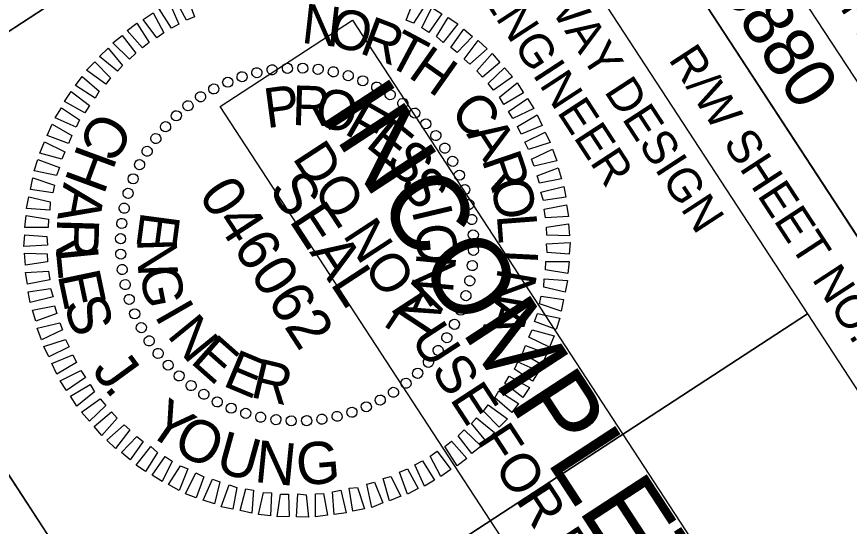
# Model space of a CAD drawing. Extents: x 1639622 to 2864602, y 842655 to 973236.
# Drawn here: x 1641227.1 to 1641350.8, y 843286.8 to 843362.5 of the extents above; entities that cross this region are included whole.
import ezdxf

# ---------------------------------------------------------------- set-up
doc = ezdxf.new("R2010")
doc.units = 0
for name, color, linetype in [('Default', 7, 'Continuous'), ('Old_Level_2', 7, 'Continuous'), ('Sheet Data Field CELL', 7, 'Continuous'), ('Sheet Plan CELL', 7, 'Continuous'), ('Sheet Sticker Exception Certification CELL', 7, 'Continuous'), ('Sheet Sticker Incomplete CELL', 7, 'Continuous')]:
    doc.layers.add(name, color=color, linetype=linetype)

msp = doc.modelspace()

# ---------------------------------------------------------------- linework, layer by layer
at = {"layer": 'Old_Level_2'}
for p, q in [((1641265.06, 843354.65), (1641265.06, 843354.65)), ((1641267.33, 843354.93), (1641267.33, 843354.93)), ((1641269.63, 843354.91), (1641269.63, 843354.91)), ((1641271.93, 843354.76), (1641271.93, 843354.76)), ((1641260.57, 843353.63), (1641260.57, 843353.63)), ((1641262.8, 843354.26), (1641262.8, 843354.26)), ((1641274.15, 843354.38), (1641274.15, 843354.38)), ((1641276.42, 843353.83), (1641276.42, 843353.83)), ((1641258.49, 843352.79), (1641258.49, 843352.79)), ((1641278.53, 843353.05), (1641278.53, 843353.05)), ((1641280.64, 843352.08), (1641280.64, 843352.08)), ((1641256.42, 843351.83), (1641256.42, 843351.83)), ((1641282.65, 843350.97), (1641282.65, 843350.97)), ((1641254.43, 843350.67), (1641254.43, 843350.67)), ((1641284.52, 843349.71), (1641284.52, 843349.71)), ((1641252.56, 843349.34), (1641252.56, 843349.34)), ((1641250.87, 843347.82), (1641250.87, 843347.82)), ((1641286.27, 843348.25), (1641286.27, 843348.25)), ((1641249.2, 843346.18), (1641249.2, 843346.18)), ((1641287.9, 843346.58), (1641287.9, 843346.58)), ((1641289.43, 843344.89), (1641289.43, 843344.89)), ((1641247.73, 843344.43), (1641247.73, 843344.43)), ((1641246.47, 843342.56), (1641246.47, 843342.56)), ((1641290.76, 843343.02), (1641290.76, 843343.02)), ((1641291.92, 843341.02), (1641291.92, 843341.02)), ((1641245.37, 843340.55), (1641245.37, 843340.55)), ((1641244.4, 843338.44), (1641244.4, 843338.44)), ((1641292.88, 843338.96), (1641292.88, 843338.96)), ((1641243.62, 843336.33), (1641243.62, 843336.33)), ((1641293.72, 843336.87), (1641293.72, 843336.87)), ((1641243.07, 843334.07), (1641243.07, 843334.07)), ((1641294.35, 843334.65), (1641294.35, 843334.65)), ((1641294.74, 843332.39), (1641294.74, 843332.39)), ((1641242.68, 843331.85), (1641242.68, 843331.85)), ((1641295.02, 843330.11), (1641295.02, 843330.11)), ((1641242.54, 843329.54), (1641242.54, 843329.54)), ((1641268.77, 843328.68), (1641268.77, 843328.68)), ((1641294.99, 843327.82), (1641294.99, 843327.82)), ((1641242.51, 843327.25), (1641242.51, 843327.25)), ((1641242.79, 843324.97), (1641242.79, 843324.97)), ((1641294.85, 843325.51), (1641294.85, 843325.51)), ((1641243.19, 843322.71), (1641243.19, 843322.71)), ((1641294.46, 843323.29), (1641294.46, 843323.29)), ((1641243.81, 843320.48), (1641243.81, 843320.48)), ((1641293.91, 843321.02), (1641293.91, 843321.02)), ((1641293.13, 843318.92), (1641293.13, 843318.92)), ((1641244.65, 843318.4), (1641244.65, 843318.4)), ((1641245.61, 843316.34), (1641245.61, 843316.34)), ((1641292.16, 843316.81), (1641292.16, 843316.81)), ((1641246.77, 843314.34), (1641246.77, 843314.34)), ((1641291.06, 843314.8), (1641291.06, 843314.8)), ((1641248.11, 843312.47), (1641248.11, 843312.47)), ((1641289.8, 843312.93), (1641289.8, 843312.93)), ((1641249.63, 843310.78), (1641249.63, 843310.78)), ((1641288.33, 843311.18), (1641288.33, 843311.18)), ((1641251.27, 843309.11), (1641251.27, 843309.11)), ((1641286.66, 843309.54), (1641286.66, 843309.54)), ((1641253.02, 843307.65), (1641253.02, 843307.65)), ((1641284.98, 843308.02), (1641284.98, 843308.02)), ((1641254.88, 843306.38), (1641254.88, 843306.38)), ((1641283.1, 843306.69), (1641283.1, 843306.69)), ((1641256.89, 843305.28), (1641256.89, 843305.28)), ((1641281.11, 843305.53), (1641281.11, 843305.53)), ((1641259, 843304.31), (1641259, 843304.31)), ((1641279.04, 843304.57), (1641279.04, 843304.57)), ((1641261.11, 843303.53), (1641261.11, 843303.53)), ((1641263.38, 843302.98), (1641263.38, 843302.98)), ((1641265.6, 843302.59), (1641265.6, 843302.59)), ((1641272.47, 843302.7), (1641272.47, 843302.7)), ((1641274.73, 843303.1), (1641274.73, 843303.1)), ((1641276.96, 843303.72), (1641276.96, 843303.72)), ((1641267.91, 843302.45), (1641267.91, 843302.45)), ((1641270.2, 843302.43), (1641270.2, 843302.43))]:
    msp.add_line(p, q, dxfattribs=at)
for points in [[(1641252.36, 843362.03), (1641250.74, 843364.97), (1641252.33, 843365.8), (1641253.54, 843362.51)], [(1641250.13, 843360.84), (1641248.31, 843363.71), (1641249.8, 843364.59), (1641251.23, 843361.45)], [(1641285, 843362.04), (1641286.25, 843365.23), (1641287.86, 843364.36), (1641286.08, 843361.57)], [(1641287.3, 843360.89), (1641288.79, 843363.91), (1641290.3, 843362.98), (1641288.34, 843360.2)], [(1641247.94, 843359.41), (1641245.9, 843362.14), (1641247.37, 843363.13), (1641248.98, 843360.12)], [(1641289.5, 843359.6), (1641291.25, 843362.42), (1641292.65, 843361.48), (1641290.5, 843358.69)], [(1641245.8, 843357.9), (1641243.55, 843360.48), (1641244.96, 843361.56), (1641246.78, 843358.69)], [(1641291.63, 843357.95), (1641293.55, 843360.7), (1641294.85, 843359.62), (1641292.55, 843357.24)], [(1641243.9, 843356.23), (1641241.39, 843358.64), (1641242.77, 843359.76), (1641244.82, 843357.11)], [(1641293.6, 843356.25), (1641295.71, 843359.01), (1641297.01, 843357.74), (1641294.44, 843355.49)], [(1641242.09, 843354.44), (1641239.42, 843356.61), (1641240.71, 843357.86), (1641242.82, 843355.31)], [(1641295.49, 843354.49), (1641297.79, 843357.06), (1641298.89, 843355.72), (1641296.32, 843353.54)], [(1641240.36, 843352.51), (1641237.49, 843354.6), (1641238.74, 843355.83), (1641241.07, 843353.43)], [(1641297.15, 843352.59), (1641299.6, 843354.95), (1641300.77, 843353.59), (1641297.99, 843351.64)], [(1641238.76, 843350.41), (1641235.84, 843352.29), (1641236.86, 843353.67), (1641239.37, 843351.46)], [(1641298.84, 843350.58), (1641301.5, 843352.7), (1641302.43, 843351.24), (1641299.5, 843349.51)], [(1641237.25, 843348.25), (1641234.22, 843349.92), (1641235.22, 843351.43), (1641237.91, 843349.33)], [(1641300.2, 843348.47), (1641303.02, 843350.37), (1641303.94, 843348.92), (1641300.86, 843347.4)], [(1641235.97, 843346.12), (1641232.82, 843347.52), (1641233.78, 843348.99), (1641236.44, 843347.2)], [(1641301.54, 843346.22), (1641304.47, 843347.95), (1641305.18, 843346.35), (1641302.07, 843345.06)], [(1641234.83, 843343.71), (1641231.63, 843344.89), (1641232.37, 843346.59), (1641235.29, 843344.9)], [(1641302.6, 843343.9), (1641305.64, 843345.39), (1641306.39, 843343.82), (1641303.18, 843342.78)], [(1641233.82, 843341.38), (1641230.56, 843342.27), (1641231.26, 843343.94), (1641234.29, 843342.46)], [(1641303.62, 843341.37), (1641306.73, 843342.85), (1641307.38, 843341.14), (1641304.02, 843340.32)], [(1641233.01, 843338.94), (1641229.72, 843339.61), (1641230.27, 843341.31), (1641233.47, 843340.13)], [(1641304.47, 843338.91), (1641307.59, 843340.08), (1641308.07, 843338.45), (1641304.78, 843337.8)], [(1641232.48, 843336.37), (1641229.18, 843336.85), (1641229.52, 843338.59), (1641232.73, 843337.48)], [(1641305.01, 843336.44), (1641308.41, 843337.29), (1641308.71, 843335.73), (1641305.38, 843335.24)], [(1641232.02, 843333.78), (1641228.57, 843334.03), (1641228.9, 843335.77), (1641232.11, 843335.04)], [(1641305.51, 843333.93), (1641308.79, 843334.58), (1641309.1, 843332.83), (1641305.67, 843332.66)], [(1641231.79, 843331.23), (1641228.33, 843331.21), (1641228.52, 843332.99), (1641231.84, 843332.46)], [(1641305.86, 843331.27), (1641309.12, 843331.77), (1641309.26, 843329.97), (1641305.9, 843330.09)], [(1641231.7, 843328.57), (1641228.16, 843328.39), (1641228.31, 843330.13), (1641231.57, 843329.88)], [(1641305.83, 843328.79), (1641309.37, 843328.97), (1641309.23, 843327.23), (1641305.96, 843327.48)], [(1641231.67, 843326.09), (1641228.41, 843325.59), (1641228.27, 843327.39), (1641231.64, 843327.27)], [(1641305.74, 843326.13), (1641309.2, 843326.14), (1641309.02, 843324.37), (1641305.69, 843324.9)], [(1641232.03, 843323.43), (1641228.74, 843322.78), (1641228.44, 843324.53), (1641231.86, 843324.7)], [(1641305.51, 843323.58), (1641308.97, 843323.33), (1641308.63, 843321.59), (1641305.42, 843322.32)], [(1641232.53, 843320.92), (1641229.12, 843320.07), (1641228.82, 843321.63), (1641232.15, 843322.12)], [(1641305.05, 843320.99), (1641308.35, 843320.51), (1641308.01, 843318.77), (1641304.8, 843319.88)], [(1641233.07, 843318.44), (1641229.94, 843317.28), (1641229.47, 843318.91), (1641232.75, 843319.56)], [(1641304.52, 843318.42), (1641307.82, 843317.75), (1641307.27, 843316.05), (1641304.07, 843317.23)], [(1641233.91, 843315.99), (1641230.81, 843314.51), (1641230.15, 843316.22), (1641233.51, 843317.04)], [(1641303.71, 843315.98), (1641306.97, 843315.09), (1641306.27, 843313.42), (1641303.24, 843314.9)], [(1641234.93, 843313.46), (1641231.9, 843311.97), (1641231.15, 843313.54), (1641234.36, 843314.58)], [(1641302.7, 843313.65), (1641305.9, 843312.47), (1641305.16, 843310.77), (1641302.25, 843312.46)], [(1641235.99, 843311.14), (1641233.06, 843309.41), (1641232.35, 843311.01), (1641235.46, 843312.3)], [(1641301.56, 843311.24), (1641304.72, 843309.84), (1641303.76, 843308.37), (1641301.09, 843310.16)], [(1641237.33, 843308.89), (1641234.52, 843306.98), (1641233.59, 843308.44), (1641236.67, 843309.96)], [(1641300.28, 843309.11), (1641303.31, 843307.43), (1641302.31, 843305.93), (1641299.63, 843308.03)], [(1641238.7, 843306.78), (1641236.03, 843304.66), (1641235.1, 843306.12), (1641238.03, 843307.85)], [(1641298.78, 843306.95), (1641301.69, 843305.07), (1641300.67, 843303.69), (1641298.16, 843305.9)], [(1641240.38, 843304.77), (1641237.93, 843302.41), (1641236.76, 843303.77), (1641239.54, 843305.72)], [(1641242.05, 843302.86), (1641239.75, 843300.29), (1641238.65, 843301.64), (1641241.21, 843303.82)], [(1641297.17, 843304.85), (1641300.04, 843302.75), (1641298.79, 843301.53), (1641296.47, 843303.93)], [(1641295.44, 843302.92), (1641298.11, 843300.75), (1641296.82, 843299.5), (1641294.71, 843302.05)], [(1641243.93, 843301.11), (1641241.82, 843298.35), (1641240.52, 843299.62), (1641243.1, 843301.87)], [(1641245.9, 843299.41), (1641243.98, 843296.66), (1641242.68, 843297.74), (1641244.98, 843300.12)], [(1641293.63, 843301.13), (1641296.14, 843298.72), (1641294.76, 843297.6), (1641292.71, 843300.25)], [(1641291.73, 843299.46), (1641293.98, 843296.88), (1641292.57, 843295.79), (1641290.75, 843298.67)], [(1641248.03, 843297.76), (1641246.28, 843294.93), (1641244.88, 843295.88), (1641247.04, 843298.67)], [(1641289.59, 843297.95), (1641291.63, 843295.22), (1641290.16, 843294.22), (1641288.56, 843297.24)], [(1641250.23, 843296.47), (1641248.75, 843293.45), (1641247.23, 843294.38), (1641249.2, 843297.16)], [(1641287.4, 843296.52), (1641289.22, 843293.65), (1641287.73, 843292.77), (1641286.3, 843295.91)], [(1641252.53, 843295.32), (1641251.28, 843292.13), (1641249.68, 843293), (1641251.45, 843295.79)], [(1641285.18, 843295.33), (1641286.79, 843292.39), (1641285.2, 843291.56), (1641283.99, 843294.84)], [(1641254.9, 843294.14), (1641253.78, 843291.05), (1641252.2, 843291.62), (1641253.74, 843294.75)], [(1641282.73, 843294.18), (1641284.21, 843291.26), (1641282.53, 843290.57), (1641281.59, 843293.91)], [(1641257.32, 843293.38), (1641256.5, 843290.11), (1641254.8, 843290.66), (1641256.2, 843293.82)], [(1641259.83, 843292.56), (1641259.22, 843289.36), (1641257.48, 843289.7), (1641258.67, 843292.97)], [(1641280.27, 843293.34), (1641281.53, 843290.27), (1641279.9, 843289.61), (1641279.13, 843293.07)], [(1641262.32, 843292.16), (1641262.04, 843288.75), (1641260.31, 843289.15), (1641261.15, 843292.38)], [(1641264.99, 843291.76), (1641264.82, 843288.36), (1641263.05, 843288.55), (1641263.8, 843291.83)], [(1641267.51, 843291.57), (1641267.62, 843288.24), (1641265.81, 843288.21), (1641266.31, 843291.58)], [(1641270.12, 843291.45), (1641270.47, 843288.14), (1641268.67, 843288.19), (1641268.87, 843291.61)], [(1641272.69, 843291.67), (1641273.28, 843288.47), (1641271.5, 843288.21), (1641271.51, 843291.63)], [(1641275.27, 843292.15), (1641276.09, 843288.8), (1641274.31, 843288.53), (1641274.02, 843291.94)], [(1641277.76, 843292.58), (1641278.8, 843289.37), (1641277.07, 843289.02), (1641276.53, 843292.44)]]:
    msp.add_lwpolyline(points, close=True, dxfattribs=at)
for centre, major_axis in [((1641262.81, 843354.22), (-0.171, 0.733)), ((1641265.06, 843354.64), (-0.106, 0.745)), ((1641267.34, 843354.87), (-0.041, 0.752)), ((1641269.62, 843354.89), (0.025, 0.753)), ((1641271.91, 843354.72), (0.09, 0.748)), ((1641274.16, 843354.35), (0.155, 0.737)), ((1641276.38, 843353.78), (0.219, 0.721)), ((1641258.47, 843352.8), (-0.296, 0.692)), ((1641260.61, 843353.61), (-0.234, 0.716)), ((1641278.54, 843353.02), (0.281, 0.699)), ((1641256.4, 843351.81), (-0.355, 0.664)), ((1641280.62, 843352.07), (0.34, 0.672)), ((1641254.43, 843350.64), (-0.411, 0.631)), ((1641282.62, 843350.95), (0.398, 0.639)), ((1641252.57, 843349.31), (-0.465, 0.592)), ((1641284.5, 843349.66), (0.452, 0.602)), ((1641250.84, 843347.82), (-0.515, 0.55)), ((1641286.27, 843348.21), (0.503, 0.561)), ((1641287.91, 843346.61), (0.55, 0.515)), ((1641249.24, 843346.19), (-0.561, 0.503)), ((1641247.79, 843344.42), (-0.602, 0.452)), ((1641289.4, 843344.87), (0.592, 0.465)), ((1641246.49, 843342.53), (-0.639, 0.398)), ((1641290.73, 843343.01), (0.631, 0.411)), ((1641245.37, 843340.54), (-0.672, 0.34)), ((1641291.9, 843341.04), (0.664, 0.355)), ((1641292.89, 843338.98), (0.692, 0.296)), ((1641244.43, 843338.45), (-0.699, 0.281)), ((1641293.69, 843336.84), (0.716, 0.234)), ((1641243.67, 843336.29), (-0.721, 0.219)), ((1641243.1, 843334.08), (-0.737, 0.155)), ((1641294.31, 843334.64), (0.733, 0.171)), ((1641242.73, 843331.82), (-0.748, 0.09)), ((1641294.73, 843332.39), (0.745, 0.106)), ((1641242.55, 843329.54), (-0.753, 0.025)), ((1641294.96, 843330.11), (0.752, 0.041)), ((1641294.98, 843327.82), (0.753, -0.025)), ((1641242.58, 843327.25), (-0.752, -0.041)), ((1641294.81, 843325.54), (0.748, -0.09)), ((1641242.8, 843324.97), (-0.745, -0.106)), ((1641294.43, 843323.28), (0.737, -0.155)), ((1641243.22, 843322.72), (-0.733, -0.171)), ((1641243.84, 843320.52), (-0.716, -0.234)), ((1641293.87, 843321.07), (0.721, -0.219)), ((1641244.65, 843318.38), (-0.692, -0.296)), ((1641293.11, 843318.91), (0.699, -0.281)), ((1641292.16, 843316.82), (0.672, -0.34)), ((1641245.64, 843316.32), (-0.664, -0.355)), ((1641246.8, 843314.35), (-0.631, -0.411)), ((1641291.04, 843314.83), (0.639, -0.398)), ((1641289.75, 843312.94), (0.602, -0.452)), ((1641248.13, 843312.49), (-0.592, -0.465)), ((1641249.62, 843310.75), (-0.55, -0.515)), ((1641288.3, 843311.17), (0.561, -0.503)), ((1641251.26, 843309.15), (-0.503, -0.561)), ((1641286.7, 843309.54), (0.515, -0.55)), ((1641284.96, 843308.05), (0.465, -0.592)), ((1641253.03, 843307.7), (-0.452, -0.602)), ((1641283.1, 843306.71), (0.411, -0.631)), ((1641254.92, 843306.41), (-0.398, -0.639)), ((1641281.13, 843305.55), (0.355, -0.664)), ((1641256.91, 843305.28), (-0.34, -0.672)), ((1641258.99, 843304.34), (-0.281, -0.699)), ((1641279.07, 843304.56), (0.296, -0.692)), ((1641261.15, 843303.58), (-0.219, -0.721)), ((1641263.37, 843303.01), (-0.155, -0.737)), ((1641274.72, 843303.14), (0.171, -0.733)), ((1641276.93, 843303.75), (0.234, -0.716)), ((1641265.63, 843302.64), (-0.09, -0.748)), ((1641267.91, 843302.47), (-0.025, -0.753)), ((1641270.2, 843302.49), (0.041, -0.752)), ((1641272.47, 843302.72), (0.106, -0.745))]:
    msp.add_ellipse(centre, major_axis=major_axis, ratio=0.999708, dxfattribs=at)
at = {"layer": 'Sheet Plan CELL'}
for p, q in [((1641310.9, 843415.83), (1641420.21, 843248.29)), ((1641300.41, 843408.97), (1641409.74, 843241.46)), ((1641300.41, 843408.97), (1641409.74, 843241.46)), ((1641344.62, 843318.36), (1641250.45, 843256.89))]:
    msp.add_line(p, q, dxfattribs=at)
for points in [[(1639731.66, 843937.55), (1640610.97, 844511.36), (1641321.42, 843422.68), (1641195.75, 843340.66), (1641305.06, 843173.13), (1640551.38, 842681.33)], [(1641321.42, 843422.68), (1641430.74, 843255.12), (1641409.74, 843241.46), (1641300.41, 843408.97)], [(1641289.95, 843402.15), (1641344.62, 843318.36), (1641250.4, 843256.87), (1641195.75, 843340.66)], [(1641344.62, 843318.36), (1641399.27, 843234.63), (1641305.06, 843173.13), (1641250.4, 843256.87)]]:
    msp.add_lwpolyline(points, close=True, dxfattribs=at)
at = {"layer": 'Sheet Sticker Exception Certification CELL'}
msp.add_line((1641195.75, 843340.66), (1641305.07, 843173.14), dxfattribs=at)
msp.add_line((1641195.75, 843340.66), (1641305.07, 843173.14), dxfattribs=at)
at = {"layer": 'Sheet Sticker Incomplete CELL'}
msp.add_lwpolyline([(1641257.35, 843349.17), (1641277.03, 843362.02), (1641357.36, 843238.91), (1641337.68, 843226.06)], close=True, dxfattribs=at)

# ---------------------------------------------------------------- texts
at = {"layer": 'Default'}
for s, rotation, p in [('C', 240.3258, (1641239.17, 843348.91)), ('H', 249.7695, (1641236.25, 843343.78)), ('A', 259.6093, (1641234.14, 843338)), ('R', 268.322, (1641233.13, 843332.65)), ('L', 275.6942, (1641232.91, 843328.05)), ('E', 281.8784, (1641233.18, 843324.19)), ('S', 288.885, (1641233.99, 843319.88)), ('J', 306.158, (1641238.17, 843309.96)), ('.', 311.3399, (1641239.98, 843307.27)), ('Y', 325.3685, (1641246.03, 843300.93)), ('O', 333.1672, (1641250, 843298.1)), ('U', 344.5606, (1641256.41, 843295)), ('N', 354.3548, (1641262.31, 843293.39)), ('G', 4.9257, (1641268.89, 843292.81))]:
    msp.add_text(s, height=6.27, rotation=rotation, dxfattribs=at).set_placement(p)
at = {"layer": 'Old_Level_2'}
for s, height, rotation, p in [('N', 5.9, 353.5494, (1641269.29, 843358.66)), ('O', 5.9, 346.3476, (1641273.15, 843358.37)), ('R', 5.9, 339.1464, (1641277.86, 843357.2)), ('T', 5.9, 331.9457, (1641281.76, 843355.55)), ('H', 5.9, 324.7454, (1641285.09, 843353.7)), ('P', 5.9, 7.5248, (1641264.26, 843345.96)), ('R', 5.9, 358.1656, (1641267.96, 843346.45)), ('O', 5.9, 348.8071, (1641271.11, 843346.38)), ('C', 5.9, 310.3458, (1641291.28, 843348.3)), ('F', 5.9, 330.0929, (1641275.6, 843345.25)), ('E', 5.9, 320.737, (1641278.78, 843343.36)), ('A', 5.9, 303.1462, (1641293.86, 843345.06)), ('S', 5.9, 311.3815, (1641281.71, 843340.99)), ('R', 5.9, 288.747, (1641296.15, 843341.3)), ('S', 5.9, 302.0263, (1641283.87, 843337.9)), ('046062', 6.275, 303.1259, (1641254.01, 843336.06)), ('SEAL', 6.273, 303.1259, (1641264.44, 843336.93)), ('O', 5.9, 281.5471, (1641297.47, 843337.96)), ('I', 5.9, 283.3155, (1641285.78, 843333.77)), ('E', 5.9, 262.4028, (1641245.6, 843333.7)), ('L', 5.9, 274.3468, (1641298.45, 843333.07)), ('O', 5.9, 273.9594, (1641286.35, 843331.63)), ('N', 5.9, 271.7599, (1641245.02, 843329.51)), ('I', 5.9, 267.146, (1641298.75, 843328.15)), ('N', 5.9, 264.6025, (1641286.58, 843327.55)), ('G', 5.9, 281.1161, (1641245.3, 843324.9)), ('N', 5.9, 259.9448, (1641298.67, 843325.38)), ('A', 5.9, 245.8862, (1641286.01, 843323.56)), ('I', 5.9, 299.8271, (1641247.5, 843318.12)), ('A', 5.9, 252.7431, (1641297.84, 843321.1)), ('L', 5.9, 236.5268, (1641284.16, 843319.85)), ('N', 5.9, 309.1823, (1641249.33, 843315.13)), ('E', 5.9, 318.5377, (1641252.76, 843311.2)), ('E', 5.9, 337.25, (1641257.56, 843307.75)), ('R', 5.9, 346.6073, (1641261.67, 843306.06))]:
    msp.add_text(s, height=height, rotation=rotation, dxfattribs=at).set_placement(p)
at = {"layer": 'Sheet Data Field CELL'}
msp.add_text('I-5880', height=7.5, rotation=303.1259, dxfattribs=at).set_placement((1641327.79, 843372.07))
at = {"layer": 'Sheet Plan CELL'}
for s, height, p in [('PROJECT REFERENCE NO.', 5.0001, (1641326.24, 843399.32)), ('ROADWAY DESIGN', 5.0001, (1641294.42, 843381.93)), ('ENGINEER', 5, (1641295.75, 843366.1)), ('R/W SHEET NO.', 5.0001, (1641323.86, 843356.22))]:
    msp.add_text(s, height=height, rotation=303.1259, dxfattribs=at).set_placement(p)
at = {"layer": 'Sheet Sticker Exception Certification CELL'}
for s, p in [('DOCUMENT NOT CONSIDERED FINAL', (1641198.6, 843317.37)), ('DOCUMENT NOT CONSIDERED FINAL', (1641198.6, 843317.37)), ('UNLESS ALL SIGNATURES COMPLETED', (1641188.46, 843316.8)), ('UNLESS ALL SIGNATURES COMPLETED', (1641188.46, 843316.8))]:
    msp.add_text(s, height=5.5, rotation=303.1259, dxfattribs=at).set_placement(p)
at = {"layer": 'Sheet Sticker Incomplete CELL'}
for s, height, p in [('INCOMPLETE PLANS', 11.52, (1641272.04, 843348.07)), ('DO NOT USE FOR R/W ACQUISITION', 5.76, (1641267.99, 843341.55))]:
    msp.add_text(s, height=height, rotation=303.1259, dxfattribs=at).set_placement(p)

doc.saveas('drawing.dxf')
